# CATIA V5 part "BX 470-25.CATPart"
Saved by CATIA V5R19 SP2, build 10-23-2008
Part number: BX 470-25
Bounding box of the stored display mesh (mm): x -37.351 to 37.351, y -37.351 to 37.351, z 0 to 135
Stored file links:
  C:\Users\Bora\Desktop\3D Katı model\BX serisi\BX 470\BX 470-25.CATPart
  C:\Program Files\Dassault Systemes\B19\intel_a\reffiles\standard\MetricThickPitch.txt
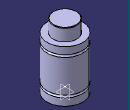
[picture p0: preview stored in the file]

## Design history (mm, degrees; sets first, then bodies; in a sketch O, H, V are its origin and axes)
Body1 (main body)
  Sketch1 on yz-plane, origin (0, 0, 0), H (0, 1, 0), V (0, 0, 1)
    point P2 (37.5, 15.5)
    line L1 (37.5, 15.5) -> (37.5, 0)
    point P3 (37.5, 20.5)
    point P4 (37.5, 89.5)
    line L2 (37.5, 89.5) -> (37.5, 20.5)
    point P6 (25, 134)
    arc A1 centre (24, 134) radius 1 from (25, 134) to (24, 135) ccw
    point P8 (25, 134)
    line L3 (25, 134) -> (25, 109)
    point P9 (37.5, 94.5)
    line L4 (37.5, 109) -> (37.5, 94.5)
    point P11 (37.5, 15.5)
    point P12 (37.5, 20.5)
    arc A2 centre (37.5, 18) radius 2.5 from (37.5, 20.5) to (37.5, 15.5) ccw
    point P13 (37.5, 89.5)
    point P14 (37.5, 94.5)
    arc A3 centre (37.5, 92) radius 2.5 from (37.5, 94.5) to (37.5, 89.5) ccw
    line L5 (24, 135) -> (0, 135)
    point P15 (0, 135)
    line L6 (25, 109) -> (37.5, 109)
    line L7 (37.5, 0) -> (0, 0)
    tangency: L5 A1
    coincidence: P15 V, P2 P11, P3 P12, P4 P13, P6 P8, P9 P14
    horizontal: L6 H, L7 H
  Shaft1: profile Sketch1, axis Sketch1.V, angle 360
  Sketch2 on face of Shaft1 from Sketch1.L7, origin (0, 0, 0), H (1, 0, 0), V (0, -1, 0)
    point P1 (20, 0)
    distance P1 V = 20
  Hole1: placed by Sketch2, at (20, 0, 0) direction (0, 0, 1), diameter 6.647, depth 7, threaded "M8", thread diameter 8, thread depth 7, pitch 1.25
  CircPattern1: of Hole1, instances 4, angular step 90, axis from xy-plane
